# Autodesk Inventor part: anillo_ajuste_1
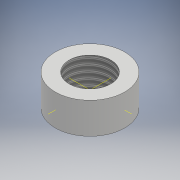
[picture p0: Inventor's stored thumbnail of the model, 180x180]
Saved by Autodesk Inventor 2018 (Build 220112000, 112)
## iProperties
Created: 2019-01
Part Number: anillo_ajuste_1
Material: Generic
Document SubType Name: Modeling
Designer: Gordillo
Density: 1 g/cm^3
Appearance: Default
Author: Gordillo
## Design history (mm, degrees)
sketch "Sketch1"
  geometry: L1 (0, -14)-(0, 14) reference; L2 (-14, 0)-(14, 0) reference; C1 r 10 at (0, 0); C2 r 6 at (0, 0); 1 further point
  constraints: 2 centre point, 2 coincident
  dimensions: "d0" = 20 diameter of C1; "d1" = 12 diameter of C2
extrude "Extrusion1" new body sketch "Sketch1" stored distance "d2" = 9; taper "d3" = 0 deg
thread "Thread1" dims "d4" = 10, "d5" = 0
body "Solid1"
